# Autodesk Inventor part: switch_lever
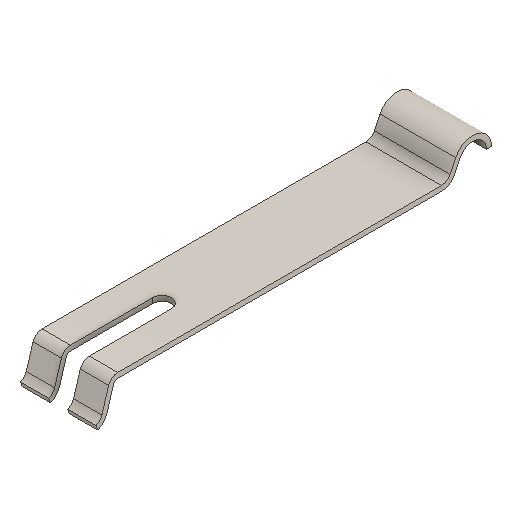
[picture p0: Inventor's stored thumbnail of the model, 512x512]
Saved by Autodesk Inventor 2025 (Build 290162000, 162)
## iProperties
Created: 2025-10
Part Number: switch_lever
Material: Generico
Document SubType Name: Modeling
Designer: Ryzen5700u
Density: 1 g/cm^3
Appearance: Default
Author: Ryzen5700u
Revision Number: ANY
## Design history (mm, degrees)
feature "Cut-Extrude1"
node "Solido1"
